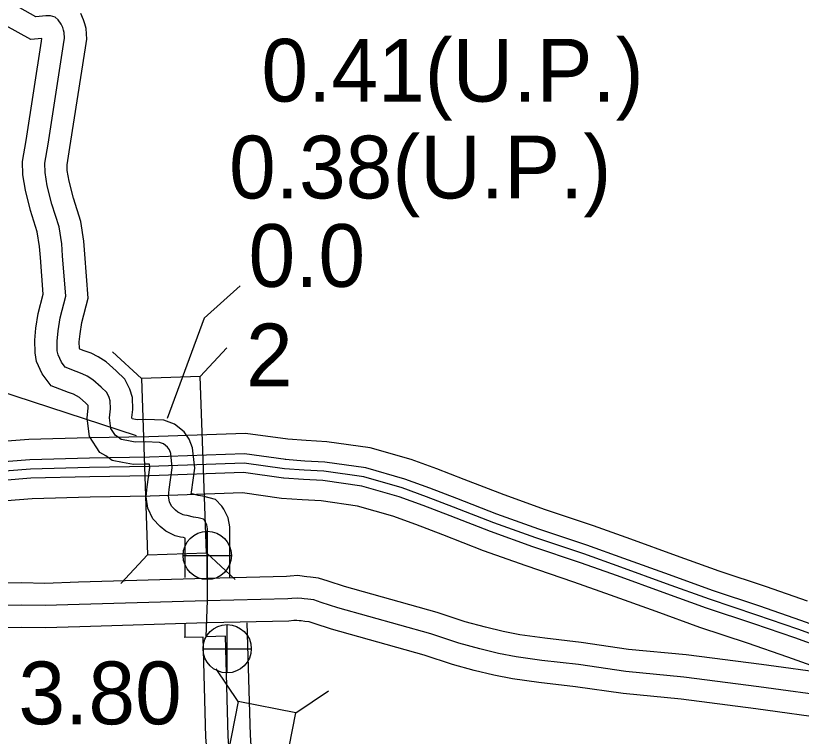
# Model space of a CAD drawing. Extents: x -83719 to 153526, y -11835 to 11446.
# Drawn here: x -2607.8 to -2431.5, y 1468.1 to 1629.8 of the extents above; entities that cross this region are included whole.
import ezdxf

# ---------------------------------------------------------------- set-up
doc = ezdxf.new("R2010")
doc.units = 0
for name, color, linetype in [('Level 11', 7, 'Continuous'), ('Level 15', 7, 'Continuous'), ('Level 19', 7, 'Continuous'), ('Level 20', 7, 'Continuous'), ('Level 25', 7, 'Continuous'), ('Level 26', 7, 'Continuous'), ('Level 58', 7, 'Continuous'), ('Level 59', 7, 'Continuous')]:
    doc.layers.add(name, color=color, linetype=linetype)

msp = doc.modelspace()

# ---------------------------------------------------------------- linework, layer by layer
at = {"layer": 'Level 11'}
for points in [[(-2559.77, 1503.79), (-2559.77, 1515.11), (-2560.13, 1517.09), (-2561.08, 1519.04), (-2561.55, 1519.71), (-2562.98, 1521.27), (-2565.84, 1522), (-2566.85, 1522.16), (-2568.43, 1522.6), (-2568.4, 1522.87), (-2567.64, 1528.26), (-2568.11, 1532.81), (-2568.9, 1534.74), (-2570.03, 1536.42), (-2572.21, 1538.17), (-2574.6, 1539.01), (-2578.76, 1539.18), (-2580.58, 1539.13), (-2581.71, 1539.34), (-2581.74, 1539.62), (-2581.56, 1541.42), (-2581.65, 1544.16), (-2582.19, 1546), (-2583.34, 1548.21), (-2585.26, 1550.12), (-2587.52, 1552.14), (-2589.32, 1553.26), (-2590.93, 1554.06), (-2592.49, 1554.63), (-2593.44, 1554.99), (-2593.5, 1555.14), (-2593.55, 1556.62), (-2593.37, 1558.42), (-2592.98, 1560.96), (-2591.55, 1566.41), (-2592.33, 1576.26), (-2592.52, 1579.17), (-2593.23, 1583.58), (-2594.89, 1588.86), (-2595.86, 1592.67), (-2596.26, 1595.08), (-2596.3, 1596.35), (-2595.65, 1600.2), (-2592.16, 1622.55), (-2591.86, 1624.56), (-2592, 1626.89), (-2592.31, 1627.94), (-2592.59, 1628.87), (-2593.21, 1630.27)], [(-2569.77, 1503.72), (-2569.77, 1512.59), (-2570.2, 1512.71), (-2570.85, 1512.76), (-2572.03, 1513.12), (-2574.13, 1514.12), (-2575.38, 1515.16), (-2577.08, 1516.89), (-2578.14, 1519.27), (-2578.56, 1521.87), (-2578.33, 1524.09), (-2577.71, 1528.44), (-2577.79, 1529.13), (-2578.81, 1529.17), (-2581.38, 1529.1), (-2583.87, 1529.57), (-2586.21, 1530.02), (-2587.57, 1531.05), (-2588.93, 1531.82), (-2591.28, 1535.35), (-2591.81, 1539.48), (-2591.58, 1541.77), (-2591.6, 1542.32), (-2592.11, 1542.84), (-2593.54, 1544.11), (-2594.19, 1544.52), (-2594.88, 1544.85), (-2596.01, 1545.27), (-2599.88, 1546.76), (-2601.9, 1549.45), (-2603.15, 1552.19), (-2603.48, 1554.14), (-2603.57, 1556.98), (-2603.29, 1559.68), (-2602.79, 1562.98), (-2601.65, 1567.31), (-2602.3, 1575.53), (-2602.47, 1578.03), (-2602.99, 1581.27), (-2604.51, 1586.12), (-2605.66, 1590.61), (-2606.24, 1594.11), (-2606.33, 1597.05), (-2605.52, 1601.81), (-2602.05, 1624.06), (-2601.96, 1624.66), (-2604.4, 1624.47), (-2610.09, 1627.6)], [(-2546.07, 1459.43), (-2548.78, 1459.14), (-2549.21, 1459.19), (-2550.13, 1459.31), (-2556.62, 1460.58), (-2554.81, 1463.67), (-2555.15, 1468.37), (-2555.85, 1493.6)], [(-2569.77, 1490.28), (-2569.77, 1493.33)], [(-2545.51, 1449.43), (-2548.93, 1449.06), (-2550.51, 1449.28), (-2551.72, 1449.43), (-2563.25, 1451.69), (-2564.62, 1451.88), (-2565.58, 1452.07), (-2567.83, 1452.9), (-2569.39, 1454.96), (-2570.06, 1457.01), (-2570.13, 1459.19), (-2569.44, 1461.79), (-2567.41, 1463.95), (-2566.26, 1464.96), (-2565.01, 1466.18), (-2565.14, 1467.88), (-2565.76, 1490.38)], [(-2565.76, 1490.38), (-2570.05, 1490.28)]]:
    msp.add_lwpolyline(points, dxfattribs=at)
at = {"layer": 'Level 15'}
for points in [[(-2547.06, 1503.96), (-2565.04, 1503.53), (-2593.74, 1502.68), (-2601.27, 1502.42), (-2606.45, 1502.52), (-2613.41, 1502.41), (-2660.97, 1502.58), (-2684.27, 1502.76), (-2696.95, 1502.71), (-2707.58, 1502.51), (-2722.15, 1502.56), (-2740.7, 1502.83), (-2747.31, 1502.86), (-2751.13, 1503.04), (-2758.11, 1504.06), (-2765.65, 1505.71)], [(-2425.11, 1482.09), (-2440.41, 1484.19), (-2457.32, 1486.36), (-2470.29, 1487.61), (-2480.88, 1489.13), (-2489.09, 1490.1), (-2494.68, 1490.88), (-2498.42, 1491.61), (-2502.41, 1492.56), (-2506.93, 1493.8), (-2513.21, 1495.86), (-2534.05, 1501.7), (-2537.72, 1502.9), (-2539.86, 1503.61), (-2541.65, 1503.8), (-2542.45, 1503.92), (-2543.06, 1503.98), (-2544.51, 1504.15), (-2546.21, 1504.03), (-2547.06, 1503.96)], [(-2546.51, 1493.97), (-2564.77, 1493.54), (-2593.42, 1492.69), (-2601.19, 1492.41), (-2606.47, 1492.52), (-2613.35, 1492.41), (-2661.03, 1492.58), (-2684.29, 1492.76), (-2696.84, 1492.71), (-2707.51, 1492.51), (-2722.24, 1492.56), (-2740.8, 1492.83), (-2747.58, 1492.86), (-2752.1, 1493.08), (-2759.9, 1494.22), (-2767.46, 1495.87)], [(-2424.39, 1471.9), (-2441.72, 1474.27), (-2458.44, 1476.42), (-2471.48, 1477.68), (-2482.18, 1479.22), (-2490.37, 1480.18), (-2496.33, 1481.02), (-2500.54, 1481.83), (-2504.9, 1482.88), (-2509.81, 1484.22), (-2516.12, 1486.29), (-2536.95, 1492.13), (-2540.84, 1493.4), (-2541.98, 1493.78), (-2542.92, 1493.88), (-2543.73, 1494), (-2544.18, 1494.05), (-2544.74, 1494.11), (-2545.43, 1494.06), (-2546.51, 1493.97)]]:
    msp.add_lwpolyline(points, dxfattribs=at)
at = {"layer": 'Level 19'}
for points in [[(-2546.75, 1534.75), (-2556.22, 1536.06), (-2577.94, 1535.29), (-2591.37, 1535.11), (-2604.9, 1534.73), (-2618.51, 1533.63), (-2634.42, 1532.4), (-2643.96, 1531.53), (-2652.33, 1530.28), (-2662.71, 1529.58)], [(-2430.08, 1498.44), (-2439.33, 1501.62), (-2449.92, 1505.14), (-2459.51, 1508.62), (-2469.78, 1512.33), (-2478.16, 1515.32), (-2488.9, 1518.92), (-2498.2, 1522.25), (-2507.16, 1525.71), (-2513.28, 1528.1), (-2519.04, 1530.19), (-2528.3, 1532.84), (-2538.03, 1534.2), (-2542.67, 1534.44), (-2546.75, 1534.75)], [(-2547.18, 1530.18), (-2556.46, 1531.47), (-2577.83, 1530.71), (-2591.27, 1530.53), (-2604.65, 1530.15), (-2618.15, 1529.06), (-2634.04, 1527.84), (-2643.41, 1526.98), (-2651.84, 1525.72), (-2662.38, 1525)], [(-2425.33, 1491.88), (-2431.6, 1494.12), (-2440.79, 1497.28), (-2451.42, 1500.81), (-2461.07, 1504.31), (-2471.33, 1508.02), (-2479.65, 1510.99), (-2490.4, 1514.59), (-2499.8, 1517.95), (-2508.82, 1521.43), (-2514.9, 1523.81), (-2520.45, 1525.83), (-2529.26, 1528.35), (-2538.47, 1529.64), (-2542.96, 1529.87), (-2547.31, 1530.2)], [(-2547.75, 1526.05), (-2556.67, 1527.29), (-2577.73, 1526.54), (-2591.18, 1526.36), (-2604.42, 1525.99), (-2617.82, 1524.91), (-2633.69, 1523.69), (-2642.91, 1522.84), (-2651.39, 1521.57), (-2662.17, 1520.84)], [(-2426.72, 1487.95), (-2432.98, 1490.19), (-2442.13, 1493.33), (-2452.79, 1496.87), (-2462.49, 1500.39), (-2472.74, 1504.09), (-2481.02, 1507.05), (-2491.76, 1510.65), (-2501.25, 1514.05), (-2510.32, 1517.55), (-2516.37, 1519.91), (-2521.74, 1521.86), (-2530.12, 1524.26), (-2538.86, 1525.48), (-2543.23, 1525.71), (-2547.62, 1526.04)], [(-2548.17, 1521.49), (-2556.9, 1522.7), (-2577.62, 1521.96), (-2591.09, 1521.78), (-2604.17, 1521.41), (-2617.46, 1520.34), (-2633.3, 1519.12), (-2642.36, 1518.28), (-2650.89, 1517.01), (-2661.84, 1516.27)], [(-2428.25, 1483.63), (-2434.49, 1485.86), (-2443.59, 1488.99), (-2454.29, 1492.54), (-2464.05, 1496.08), (-2474.29, 1499.78), (-2482.52, 1502.72), (-2493.26, 1506.32), (-2502.85, 1509.75), (-2511.98, 1513.28), (-2517.98, 1515.62), (-2523.15, 1517.5), (-2531.08, 1519.77), (-2539.3, 1520.92), (-2543.52, 1521.14), (-2548.17, 1521.49)]]:
    msp.add_lwpolyline(points, dxfattribs=at)
at = {"layer": 'Level 20'}
for p, q in [((-2579.63, 1548.37), (-2586.07, 1554.37)), ((-2566.43, 1548.84), (-2560.44, 1555.28)), ((-2578.22, 1508.8), (-2584.22, 1502.36)), ((-2565.03, 1509.27), (-2558.59, 1503.27)), ((-2557.89, 1475.91), (-2562.8, 1483.22)), ((-2544.94, 1473.37), (-2537.63, 1478.28))]:
    msp.add_line(p, q, dxfattribs=at)
for points in [[(-2565.03, 1509.27), (-2566.43, 1548.84), (-2579.63, 1548.37), (-2578.22, 1508.8)], [(-2552.56, 1434.51), (-2544.94, 1473.37), (-2557.89, 1475.91), (-2565.51, 1437.05)]]:
    msp.add_lwpolyline(points, close=True, dxfattribs=at)
at = {"layer": 'Level 25'}
for p, q in [((-2557.46, 1569.15), (-2565.51, 1561.91)), ((-2565.51, 1561.91), (-2573.82, 1539.39))]:
    msp.add_line(p, q, dxfattribs=at)
at = {"layer": 'Level 26'}
for p, q in [((-2564.83, 1503.26), (-2564.83, 1514.1)), ((-2570.25, 1508.68), (-2559.42, 1508.68)), ((-2560.37, 1482.34), (-2560.37, 1493.18)), ((-2565.79, 1487.76), (-2554.96, 1487.76))]:
    msp.add_line(p, q, dxfattribs=at)
for centre in [(-2564.83, 1508.68), (-2560.37, 1487.76)]:
    msp.add_circle(centre, 5.42, dxfattribs=at)
at = {"layer": 'Level 58'}
msp.add_line((-2613.78, 1546.36), (-2580.79, 1535.63), dxfattribs=at)
at = {"layer": 'Level 59'}
for points in [[(-2564.77, 1498.57), (-2564.77, 1514.65), (-2564.93, 1515.52), (-2565.25, 1516.18), (-2565.32, 1516.37), (-2565.46, 1516.57), (-2565.66, 1516.8), (-2566.84, 1517.1), (-2567.91, 1517.26), (-2569.32, 1517.65), (-2569.92, 1517.7), (-2570.22, 1517.79), (-2571.41, 1518.36), (-2571.99, 1518.84), (-2572.88, 1519.75), (-2573.31, 1520.71), (-2573.52, 1522), (-2573.36, 1523.48), (-2572.68, 1528.35), (-2573.01, 1531.58), (-2573.34, 1532.37), (-2573.75, 1533), (-2574.68, 1533.74), (-2575.55, 1534.04), (-2578.78, 1534.18), (-2580.98, 1534.11), (-2582.92, 1534.49), (-2584.13, 1534.72), (-2584.81, 1535.23), (-2585.42, 1535.58), (-2586.47, 1537.15), (-2586.77, 1539.55), (-2586.57, 1541.59), (-2586.62, 1543.36), (-2586.85, 1544.13), (-2587.41, 1545.21), (-2588.68, 1546.48), (-2590.53, 1548.12), (-2591.76, 1548.89), (-2592.91, 1549.46), (-2594.25, 1549.95), (-2596.75, 1550.91), (-2597.58, 1552.02), (-2598.33, 1553.67), (-2598.49, 1554.63), (-2598.56, 1556.8), (-2598.33, 1559.05), (-2597.88, 1561.97), (-2596.6, 1566.86), (-2597.31, 1575.9), (-2597.5, 1578.6), (-2598.11, 1582.42), (-2599.7, 1587.49), (-2600.76, 1591.64), (-2601.25, 1594.6), (-2601.32, 1596.7), (-2600.58, 1601), (-2597.11, 1623.31), (-2596.88, 1624.78), (-2596.96, 1626.02), (-2597.1, 1626.52), (-2597.29, 1627.15), (-2597.61, 1627.87), (-2598.28, 1628.89), (-2598.96, 1629.43), (-2600, 1629.77), (-2601.1, 1629.74), (-2603.29, 1629.57), (-2606.91, 1631.56)], [(-2547.46, 1528.12), (-2556.56, 1529.38), (-2577.78, 1528.63), (-2591.23, 1528.45), (-2604.53, 1528.07), (-2617.99, 1526.99), (-2633.86, 1525.76), (-2643.16, 1524.91), (-2651.61, 1523.64), (-2670.75, 1522.35), (-2681.05, 1521.67), (-2690.32, 1521.15), (-2700.17, 1520.81), (-2709.17, 1520.16), (-2716.29, 1519.94), (-2723.48, 1519.99), (-2731.65, 1520.17), (-2738.48, 1520.53), (-2745.52, 1520.95), (-2749.37, 1521.53), (-2753.69, 1522.37), (-2765.76, 1524.27)], [(-2426.03, 1489.92), (-2432.29, 1492.15), (-2441.46, 1495.31), (-2452.11, 1498.84), (-2461.78, 1502.35), (-2472.03, 1506.05), (-2480.34, 1509.02), (-2491.08, 1512.62), (-2500.52, 1516), (-2509.57, 1519.49), (-2515.63, 1521.86), (-2521.09, 1523.84), (-2529.69, 1526.31), (-2538.66, 1527.56), (-2543.1, 1527.79), (-2547.46, 1528.12)], [(-2546.78, 1498.96), (-2564.9, 1498.53), (-2593.58, 1497.68), (-2601.23, 1497.42), (-2606.46, 1497.52), (-2613.38, 1497.41), (-2661, 1497.58), (-2684.28, 1497.76), (-2696.9, 1497.71), (-2707.54, 1497.51), (-2722.2, 1497.56), (-2740.75, 1497.83), (-2747.44, 1497.86), (-2751.61, 1498.06), (-2759, 1499.14), (-2766.56, 1500.79)], [(-2423.45, 1476.81), (-2441.06, 1479.23), (-2457.88, 1481.39), (-2470.88, 1482.65), (-2481.53, 1484.18), (-2489.73, 1485.14), (-2495.5, 1485.95), (-2499.48, 1486.72), (-2503.66, 1487.72), (-2508.37, 1489.01), (-2514.66, 1491.08), (-2535.5, 1496.91), (-2539.28, 1498.15), (-2540.92, 1498.69), (-2542.29, 1498.84), (-2543.09, 1498.96), (-2543.62, 1499.01), (-2544.62, 1499.13), (-2545.82, 1499.05), (-2546.78, 1498.96)], [(-2545.79, 1454.43), (-2548.86, 1454.1), (-2549.86, 1454.24), (-2550.93, 1454.37), (-2562.42, 1456.62), (-2563.79, 1456.82), (-2564.22, 1456.9), (-2564.73, 1457.09), (-2564.9, 1457.32), (-2565.09, 1457.88), (-2565.11, 1458.61), (-2564.93, 1459.29), (-2563.93, 1460.35), (-2562.86, 1461.29), (-2560.82, 1463.29), (-2559.91, 1464.86), (-2560.14, 1468.13), (-2560.76, 1490.54), (-2565.05, 1490.44), (-2564.77, 1498.57)]]:
    msp.add_lwpolyline(points, dxfattribs=at)

# ---------------------------------------------------------------- texts
at = {"layer": 'Level 20'}
msp.add_text('2', height=14.08, dxfattribs=at).set_placement((-2556.13, 1546.63))
at = {"layer": 'Level 25'}
for s, p in [('0.0', (-2555.57, 1568.95)), ('3.80', (-2607.21, 1470.8))]:
    msp.add_text(s, height=14.08, dxfattribs=at).set_placement(p)
at = {"layer": 'Level 58'}
for s, p in [('0.41(U.P.)', (-2552.67, 1610.51)), ('0.38(U.P.)', (-2559.94, 1588.79))]:
    msp.add_text(s, height=14.08, dxfattribs=at).set_placement(p)

doc.saveas('drawing.dxf')
